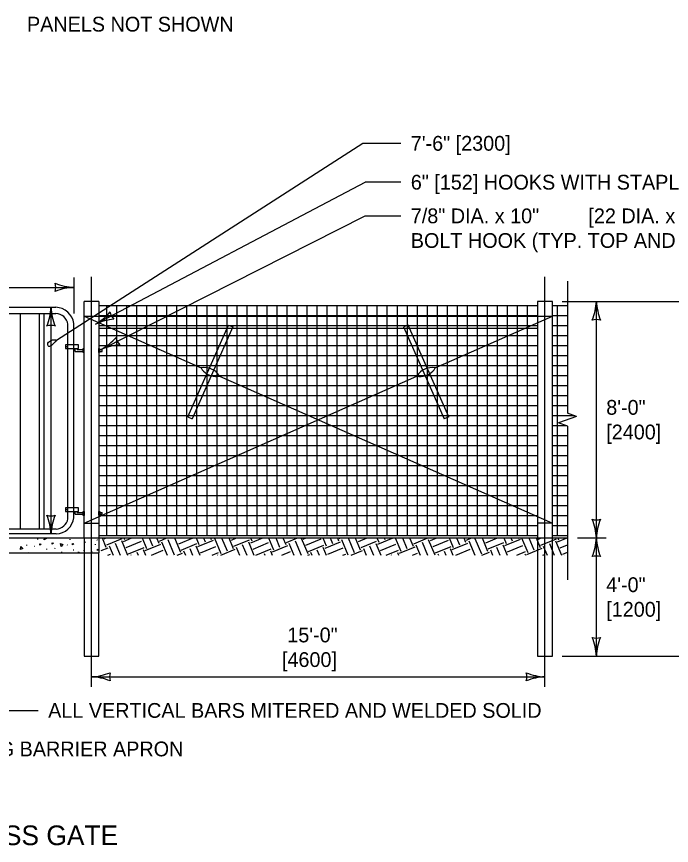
# Model space of a CAD drawing. Extents: x 49991.4 to 50021, y 49987.6 to 50011.4.
# Drawn here: x 50003.24 to 50005.896, y 49992.169 to 49995.535 of the extents above; entities that cross this region are included whole.
import ezdxf

# ---------------------------------------------------------------- set-up
doc = ezdxf.new("R2010")
doc.units = 0
for name, color, linetype in [('Level 1', 7, 'Continuous'), ('Level 2', 7, 'Continuous'), ('Level 3', 7, 'Continuous'), ('Level 4', 7, 'Continuous'), ('Level 5', 7, 'Continuous'), ('Level 6', 7, 'Continuous')]:
    doc.layers.add(name, color=color, linetype=linetype)

msp = doc.modelspace()

# ---------------------------------------------------------------- linework, layer by layer
at = {"layer": 'Level 1'}
for p, q in [((50003.5733, 49994.378), (50003.5133, 49994.378)), ((50003.5133, 49993.4177), (50003.5133, 49994.378)), ((50003.5733, 49994.378), (50003.5733, 49993.3577)), ((50005.4134, 49994.378), (50005.3534, 49994.378)), ((50005.3534, 49994.378), (50005.3534, 49993.4177)), ((50005.4134, 49993.4177), (50005.4134, 49994.378)), ((50002.8238, 49994.3543), (50003.3985, 49994.3543)), ((50005.3534, 49994.3607), (50003.5733, 49994.3607)), ((50003.6058, 49993.4259), (50003.6058, 49994.3607)), ((50003.6464, 49993.4259), (50003.6464, 49994.3607)), ((50003.6871, 49993.4259), (50003.6871, 49994.3607)), ((50003.7277, 49993.4259), (50003.7277, 49994.3607)), ((50003.7683, 49993.4259), (50003.7683, 49994.3607)), ((50003.809, 49993.4259), (50003.809, 49994.3607)), ((50003.8496, 49993.4259), (50003.8496, 49994.3607)), ((50003.8903, 49993.4259), (50003.8903, 49994.3607)), ((50003.9309, 49993.4259), (50003.9309, 49994.3607)), ((50003.9715, 49993.4259), (50003.9715, 49994.3607)), ((50004.0122, 49993.4259), (50004.0122, 49994.3607)), ((50004.0528, 49993.4259), (50004.0528, 49994.3607)), ((50004.0935, 49993.4259), (50004.0935, 49994.3607)), ((50004.1341, 49993.4259), (50004.1341, 49994.3607)), ((50004.1748, 49993.4259), (50004.1748, 49994.3607)), ((50004.2154, 49993.4259), (50004.2154, 49994.3607)), ((50004.256, 49993.4259), (50004.256, 49994.3607)), ((50004.2967, 49993.4259), (50004.2967, 49994.3607)), ((50004.3373, 49993.4259), (50004.3373, 49994.3607)), ((50004.378, 49993.4259), (50004.378, 49994.3607)), ((50004.4186, 49993.4259), (50004.4186, 49994.3607)), ((50004.4592, 49993.4259), (50004.4592, 49994.3607)), ((50004.4999, 49993.4259), (50004.4999, 49994.3607)), ((50004.5405, 49993.4259), (50004.5405, 49994.3607)), ((50004.5812, 49993.4259), (50004.5812, 49994.3607)), ((50004.6218, 49993.4259), (50004.6218, 49994.3607)), ((50004.6625, 49993.4259), (50004.6625, 49994.3607)), ((50004.7031, 49993.4259), (50004.7031, 49994.3607)), ((50004.7437, 49993.4259), (50004.7437, 49994.3607)), ((50004.7844, 49993.4259), (50004.7844, 49994.3607)), ((50004.825, 49993.4259), (50004.825, 49994.3607)), ((50004.8657, 49993.4259), (50004.8657, 49994.3607)), ((50004.9063, 49993.4259), (50004.9063, 49994.3607)), ((50004.947, 49993.4259), (50004.947, 49994.3607)), ((50004.9876, 49993.4259), (50004.9876, 49994.3607)), ((50005.0282, 49993.4259), (50005.0282, 49994.3607)), ((50005.0689, 49993.4259), (50005.0689, 49994.3607)), ((50005.1095, 49993.4259), (50005.1095, 49994.3607)), ((50005.1502, 49993.4259), (50005.1502, 49994.3607)), ((50005.1908, 49993.4259), (50005.1908, 49994.3607)), ((50005.2314, 49993.4259), (50005.2314, 49994.3607)), ((50005.2721, 49993.4259), (50005.2721, 49994.3607)), ((50005.3127, 49993.4259), (50005.3127, 49994.3607)), ((50005.4753, 49994.3607), (50005.4134, 49994.3607)), ((50005.4347, 49993.4259), (50005.4347, 49994.3607)), ((50002.8236, 49994.3293), (50003.3985, 49994.3293)), ((50003.256, 49993.4537), (50003.256, 49994.3293)), ((50003.332, 49993.4537), (50003.332, 49994.3293)), ((50003.352, 49993.4537), (50003.352, 49994.3293)), ((50003.5133, 49994.3179), (50005.4134, 49994.3179)), ((50003.5133, 49994.3179), (50003.9883, 49994.108)), ((50005.3534, 49994.32), (50003.5733, 49994.32)), ((50004.9383, 49994.1079), (50005.4134, 49994.3179)), ((50005.4753, 49994.32), (50005.4134, 49994.32)), ((50003.448, 49993.4957), (50003.448, 49994.2853)), ((50003.472, 49993.4999), (50003.472, 49994.2888)), ((50005.3534, 49994.2794), (50003.5733, 49994.2794)), ((50003.5733, 49994.27), (50005.3534, 49994.27)), ((50003.9337, 49993.9088), (50004.0989, 49994.2823)), ((50004.1172, 49994.2743), (50003.952, 49993.9007)), ((50004.0989, 49994.2823), (50004.1172, 49994.2743)), ((50004.8277, 49994.2824), (50004.8094, 49994.2743)), ((50004.8094, 49994.2743), (50004.9746, 49993.9007)), ((50004.9929, 49993.9088), (50004.8277, 49994.2824)), ((50005.4753, 49994.2794), (50005.4134, 49994.2794)), ((50005.3534, 49994.2387), (50003.5733, 49994.2387)), ((50005.4753, 49994.2387), (50005.4134, 49994.2387)), ((50003.4375, 49994.2014), (50003.4375, 49994.1866)), ((50003.4906, 49994.2014), (50003.4375, 49994.2014)), ((50003.4906, 49994.1866), (50003.4906, 49994.2014)), ((50005.3534, 49994.1981), (50003.5733, 49994.1981)), ((50005.4753, 49994.1981), (50005.4134, 49994.1981)), ((50003.4375, 49994.1866), (50003.4906, 49994.1866)), ((50003.4779, 49994.1752), (50003.4779, 49994.1866)), ((50003.4779, 49994.1752), (50003.5133, 49994.1752)), ((50003.4854, 49994.1827), (50003.4854, 49994.1866)), ((50003.4854, 49994.1827), (50003.5133, 49994.1827)), ((50003.5098, 49994.171), (50003.5098, 49994.1864)), ((50003.5098, 49994.1864), (50003.5133, 49994.1864)), ((50003.5133, 49994.171), (50003.5098, 49994.171)), ((50003.5731, 49994.1711), (50003.5731, 49994.1866)), ((50003.5731, 49994.1866), (50003.5766, 49994.1866)), ((50003.5766, 49994.1711), (50003.5731, 49994.1711)), ((50003.5733, 49994.1752), (50003.5868, 49994.1752)), ((50003.5734, 49994.1827), (50003.5868, 49994.1827)), ((50003.5766, 49994.1866), (50003.5766, 49994.1711)), ((50003.5868, 49994.175), (50003.5868, 49994.1827)), ((50005.3534, 49994.1574), (50003.5733, 49994.1574)), ((50005.4753, 49994.1574), (50005.4134, 49994.1574)), ((50005.3534, 49994.1168), (50003.5733, 49994.1168)), ((50005.4753, 49994.1168), (50005.4134, 49994.1168)), ((50003.5133, 49993.4779), (50004.864, 49994.0751)), ((50005.3534, 49994.0762), (50003.5733, 49994.0762)), ((50004.0626, 49994.0751), (50005.4134, 49993.4779)), ((50005.4753, 49994.0762), (50005.4134, 49994.0762)), ((50005.3534, 49994.0355), (50003.5733, 49994.0355)), ((50005.4753, 49994.0355), (50005.4134, 49994.0355)), ((50005.3534, 49993.9949), (50003.5733, 49993.9949)), ((50005.4753, 49993.9949), (50005.4134, 49993.9949)), ((50005.3534, 49993.9542), (50003.5733, 49993.9542)), ((50005.4753, 49993.9542), (50005.4134, 49993.9542)), ((50005.3534, 49993.9136), (50003.5733, 49993.9136)), ((50003.9337, 49993.9088), (50003.952, 49993.9007)), ((50004.9929, 49993.9088), (50004.9746, 49993.9007)), ((50005.5046, 49993.9136), (50005.4134, 49993.9136)), ((50005.3534, 49993.873), (50003.5733, 49993.873)), ((50005.473, 49993.873), (50005.4134, 49993.873)), ((50005.3534, 49993.8323), (50003.5733, 49993.8323)), ((50005.4753, 49993.8323), (50005.4134, 49993.8323)), ((50005.3534, 49993.7917), (50003.5733, 49993.7917)), ((50005.4753, 49993.7917), (50005.4134, 49993.7917)), ((50005.3534, 49993.751), (50003.5733, 49993.751)), ((50005.4753, 49993.751), (50005.4134, 49993.751)), ((50005.3534, 49993.7104), (50003.5733, 49993.7104)), ((50005.4753, 49993.7104), (50005.4134, 49993.7104)), ((50005.3534, 49993.6697), (50003.5733, 49993.6697)), ((50005.4753, 49993.6697), (50005.4134, 49993.6697)), ((50005.3534, 49993.6291), (50003.5733, 49993.6291)), ((50005.4753, 49993.6291), (50005.4134, 49993.6291)), ((50005.3534, 49993.5885), (50003.5733, 49993.5885)), ((50005.4753, 49993.5885), (50005.4134, 49993.5885)), ((50003.4779, 49993.5136), (50003.4779, 49993.525)), ((50003.4854, 49993.5211), (50003.4854, 49993.525)), ((50005.3534, 49993.5478), (50003.5733, 49993.5478)), ((50005.4753, 49993.5478), (50005.4134, 49993.5478)), ((50003.4779, 49993.5136), (50003.5133, 49993.5136)), ((50003.4854, 49993.5211), (50003.5133, 49993.5211)), ((50003.5733, 49993.5211), (50003.5868, 49993.5211)), ((50003.5733, 49993.5136), (50003.5868, 49993.5136)), ((50005.3534, 49993.5072), (50003.5733, 49993.5072)), ((50003.5868, 49993.5136), (50003.5868, 49993.5211)), ((50005.4753, 49993.5072), (50005.4134, 49993.5072)), ((50003.5133, 49993.4779), (50003.5733, 49993.4779)), ((50005.3534, 49993.4665), (50003.5733, 49993.4665)), ((50005.4134, 49993.4779), (50005.3534, 49993.4779)), ((50005.4753, 49993.4665), (50005.4134, 49993.4665)), ((50003.4, 49993.4537), (50002.8253, 49993.4537)), ((50003.4, 49993.4337), (50002.8253, 49993.4337)), ((50005.3534, 49993.4259), (50003.5733, 49993.4259)), ((50005.4753, 49993.4259), (50005.4134, 49993.4259)), ((49999.9385, 49993.4177), (50005.4753, 49993.4177)), ((50003.326, 49993.4113), (50003.3261, 49993.4134)), ((50003.4451, 49993.3898), (50003.446, 49993.3881)), ((50003.4574, 49993.4104), (50003.4575, 49993.4126)), ((50003.4913, 49993.4148), (50003.4913, 49993.4169)), ((50003.5191, 49993.3991), (50003.5191, 49993.4013)), ((50003.5595, 49993.3899), (50003.5595, 49993.392)), ((50003.5651, 49993.4096), (50003.5664, 49993.4087)), ((50003.5661, 49993.4094), (50003.5674, 49993.4086)), ((50003.5866, 49993.4177), (50003.602, 49993.3807)), ((50003.5953, 49993.4146), (50003.6028, 49993.4177)), ((50003.6056, 49993.3896), (50003.6683, 49993.4155)), ((50003.64, 49993.3965), (50003.6603, 49993.3476)), ((50003.6651, 49993.4068), (50003.6896, 49993.3476)), ((50003.6733, 49993.4034), (50003.7078, 49993.4177)), ((50003.6747, 49993.4177), (50003.6771, 49993.4118)), ((50003.6837, 49993.3784), (50003.7463, 49993.4043)), ((50003.7486, 49993.4177), (50003.7662, 49993.3754)), ((50003.7618, 49993.3667), (50003.8245, 49993.3927)), ((50003.7779, 49993.4177), (50003.7912, 49993.3857)), ((50003.8073, 49993.4177), (50003.8163, 49993.3961)), ((50003.8193, 49993.4052), (50003.8495, 49993.4177)), ((50003.8281, 49993.4015), (50003.8505, 49993.3476)), ((50003.8532, 49993.4119), (50003.8791, 49993.3493)), ((50003.8801, 49993.4177), (50003.9042, 49993.3597)), ((50003.8975, 49993.3936), (50003.9558, 49993.4177)), ((50003.9078, 49993.3685), (50003.9705, 49993.3945)), ((50003.9682, 49993.4177), (50003.9793, 49993.3908)), ((50003.9755, 49993.3824), (50004.0381, 49993.4083)), ((50003.9975, 49993.4177), (50004.0044, 49993.4012)), ((50004.0269, 49993.4177), (50004.0294, 49993.4115)), ((50004.0424, 49993.4169), (50004.0683, 49993.3543)), ((50004.0714, 49993.4177), (50004.0934, 49993.3647)), ((50004.1008, 49993.4177), (50004.1184, 49993.3751)), ((50004.1111, 49993.4092), (50004.1317, 49993.4177)), ((50004.1215, 49993.3842), (50004.1841, 49993.4101)), ((50004.1554, 49993.3909), (50004.1733, 49993.3476)), ((50004.1804, 49993.4012), (50004.2027, 49993.3476)), ((50004.1888, 49993.4177), (50004.1936, 49993.4062)), ((50004.1893, 49993.3976), (50004.238, 49993.4177)), ((50004.1997, 49993.3725), (50004.2623, 49993.3985)), ((50004.2182, 49993.4177), (50004.2186, 49993.4166)), ((50004.2616, 49993.4177), (50004.2815, 49993.3697)), ((50004.291, 49993.4177), (50004.3066, 49993.3801)), ((50004.3203, 49993.4177), (50004.3316, 49993.3905)), ((50004.3353, 49993.3994), (50004.3797, 49993.4177)), ((50004.3446, 49993.3959), (50004.3646, 49993.3476)), ((50004.3696, 49993.4062), (50004.394, 49993.3476)), ((50004.3947, 49993.4166), (50004.4206, 49993.354)), ((50004.4029, 49993.4132), (50004.4138, 49993.4177)), ((50004.4133, 49993.3882), (50004.4759, 49993.4141)), ((50004.4823, 49993.4177), (50004.4958, 49993.3851)), ((50004.4915, 49993.3765), (50004.5541, 49993.4025)), ((50004.5116, 49993.4177), (50004.5208, 49993.3955)), ((50004.541, 49993.4177), (50004.5459, 49993.4059)), ((50004.5489, 49993.415), (50004.5555, 49993.4177)), ((50004.5578, 49993.4113), (50004.5837, 49993.3487)), ((50004.5845, 49993.4177), (50004.6088, 49993.3591)), ((50004.6138, 49993.4177), (50004.6338, 49993.3694)), ((50004.6271, 49993.4034), (50004.6618, 49993.4177)), ((50004.6375, 49993.3783), (50004.7001, 49993.4042)), ((50004.6969, 49993.3956), (50004.7168, 49993.3476)), ((50004.7018, 49993.4177), (50004.709, 49993.4006)), ((50004.7051, 49993.3922), (50004.7669, 49993.4177)), ((50004.7155, 49993.3671), (50004.7781, 49993.393)), ((50004.7312, 49993.4177), (50004.734, 49993.4109)), ((50004.7757, 49993.4177), (50004.798, 49993.3641)), ((50004.8051, 49993.4177), (50004.823, 49993.3745)), ((50004.8344, 49993.4177), (50004.8481, 49993.3848)), ((50004.8511, 49993.3939), (50004.9086, 49993.4177)), ((50004.86, 49993.3903), (50004.8776, 49993.3476)), ((50004.885, 49993.4006), (50004.907, 49993.3476)), ((50004.9101, 49993.411), (50004.936, 49993.3484)), ((50004.9189, 49993.4073), (50004.944, 49993.4177)), ((50004.9225, 49993.4177), (50004.9232, 49993.416)), ((50004.9293, 49993.3823), (50004.9919, 49993.4082)), ((50004.9953, 49993.4177), (50005.0111, 49993.3795)), ((50005.0073, 49993.3711), (50005.0699, 49993.397)), ((50005.0247, 49993.4177), (50005.0362, 49993.3899)), ((50005.054, 49993.4177), (50005.0612, 49993.4003)), ((50005.0649, 49993.4091), (50005.0857, 49993.4177)), ((50005.0742, 49993.4057), (50005.0983, 49993.3476)), ((50005.0993, 49993.416), (50005.1252, 49993.3534)), ((50005.1279, 49993.4177), (50005.1503, 49993.3638)), ((50005.1429, 49993.3979), (50005.1907, 49993.4177)), ((50005.1533, 49993.3729), (50005.2159, 49993.3988)), ((50005.2122, 49993.39), (50005.2298, 49993.3476)), ((50005.216, 49993.4177), (50005.2254, 49993.3949)), ((50005.2211, 49993.3863), (50005.2837, 49993.4122)), ((50005.2453, 49993.4177), (50005.2505, 49993.4053)), ((50005.2747, 49993.4177), (50005.2755, 49993.4157)), ((50005.2888, 49993.4177), (50005.3133, 49993.3585)), ((50005.3181, 49993.4177), (50005.3384, 49993.3688)), ((50005.3475, 49993.4177), (50005.3634, 49993.3792)), ((50005.3567, 49993.4131), (50005.3678, 49993.4177)), ((50005.3671, 49993.3881), (50005.4297, 49993.414)), ((50005.4015, 49993.395), (50005.4211, 49993.3476)), ((50005.4265, 49993.4054), (50005.4505, 49993.3476)), ((50005.4347, 49993.4019), (50005.4729, 49993.4177)), ((50005.4355, 49993.4177), (50005.4386, 49993.4103)), ((50005.4451, 49993.3769), (50005.4753, 49993.3894)), ((50001.8892, 49993.3577), (50003.5733, 49993.3577)), ((50003.2805, 49993.3871), (50003.2806, 49993.3892)), ((50003.3109, 49993.3846), (50003.3121, 49993.3838)), ((50003.3616, 49993.3707), (50003.3617, 49993.3729)), ((50003.3954, 49993.3751), (50003.3955, 49993.3773)), ((50003.4232, 49993.3595), (50003.4233, 49993.3616)), ((50003.4693, 49993.3699), (50003.4706, 49993.369)), ((50003.4703, 49993.3698), (50003.4716, 49993.3689)), ((50003.514, 49993.3656), (50003.514, 49993.3677)), ((50003.5443, 49993.3632), (50003.5456, 49993.3623)), ((50003.5828, 49993.366), (50003.6107, 49993.3775)), ((50003.615, 49993.3861), (50003.6309, 49993.3476)), ((50003.694, 49993.3533), (50003.7567, 49993.3793)), ((50003.7279, 49993.36), (50003.7331, 49993.3476)), ((50003.753, 49993.3704), (50003.7624, 49993.3476)), ((50003.7864, 49993.3476), (50003.8348, 49993.3676)), ((50003.8914, 49993.3476), (50003.9128, 49993.3564)), ((50003.9172, 49993.365), (50003.9244, 49993.3476)), ((50003.9422, 49993.3754), (50003.9537, 49993.3476)), ((50003.9673, 49993.3858), (50003.9831, 49993.3476)), ((50003.9858, 49993.3573), (50004.0485, 49993.3833)), ((50004.0331, 49993.3476), (50004.0588, 49993.3582)), ((50004.0686, 49993.3476), (50004.1267, 49993.3716)), ((50004.1303, 49993.3805), (50004.144, 49993.3476)), ((50004.2103, 49993.3476), (50004.2727, 49993.3734)), ((50004.2694, 49993.3647), (50004.2766, 49993.3476)), ((50004.2777, 49993.3613), (50004.3403, 49993.3873)), ((50004.3153, 49993.3476), (50004.3507, 49993.3622)), ((50004.4237, 49993.3631), (50004.4863, 49993.389)), ((50004.4325, 49993.3594), (50004.4374, 49993.3476)), ((50004.4576, 49993.3698), (50004.4668, 49993.3476)), ((50004.4826, 49993.3802), (50004.4961, 49993.3476)), ((50004.5018, 49993.3515), (50004.5645, 49993.3774)), ((50004.5975, 49993.3476), (50004.6425, 49993.3662)), ((50004.6468, 49993.3748), (50004.6581, 49993.3476)), ((50004.6718, 49993.3852), (50004.6874, 49993.3476)), ((50004.7392, 49993.3476), (50004.7885, 49993.368)), ((50004.7848, 49993.3591), (50004.7896, 49993.3476)), ((50004.7937, 49993.3555), (50004.8563, 49993.3814)), ((50004.8454, 49993.3476), (50004.8667, 49993.3564)), ((50004.9397, 49993.3573), (50005.0023, 49993.3832)), ((50004.974, 49993.3641), (50004.9809, 49993.3476)), ((50004.9991, 49993.3745), (50005.0102, 49993.3476)), ((50005.0213, 49993.3476), (50005.0803, 49993.372)), ((50005.1276, 49993.3476), (50005.1585, 49993.3604)), ((50005.1621, 49993.3692), (50005.1711, 49993.3476)), ((50005.1872, 49993.3796), (50005.2005, 49993.3476)), ((50005.2315, 49993.3612), (50005.2941, 49993.3872)), ((50005.2693, 49993.3476), (50005.3045, 49993.3621)), ((50005.3095, 49993.3501), (50005.3721, 49993.376)), ((50005.3764, 49993.3846), (50005.3918, 49993.3476)), ((50005.4555, 49993.3518), (50005.4753, 49993.36)), ((50003.6093, 49993.3476), (50003.621, 49993.3524)), ((50003.7029, 49993.3497), (50003.7037, 49993.3476)), ((50004.0552, 49993.3494), (50004.0559, 49993.3476)), ((50004.2444, 49993.3544), (50004.2472, 49993.3476)), ((50004.4216, 49993.3476), (50004.4288, 49993.3506)), ((50004.5633, 49993.3476), (50004.5748, 49993.3524)), ((50004.7598, 49993.3488), (50004.7603, 49993.3476)), ((50004.949, 49993.3538), (50004.9515, 49993.3476)), ((50005.3013, 49993.3535), (50005.3037, 49993.3476)), ((50005.3743, 49993.3476), (50005.3825, 49993.3509)), ((50005.4643, 49993.3482), (50005.4646, 49993.3476))]:
    msp.add_line(p, q, dxfattribs=at)
for points in [[(50003.4906, 49993.525), (50003.4906, 49993.5397), (50003.4375, 49993.5397), (50003.4375, 49993.525)], [(50003.5133, 49993.5248), (50003.5133, 49993.5093), (50003.5098, 49993.5093), (50003.5098, 49993.5248)], [(50003.5768, 49993.5249), (50003.5768, 49993.5095), (50003.5733, 49993.5095), (50003.5733, 49993.5249)]]:
    msp.add_lwpolyline(points, close=True, dxfattribs=at)
for points in [[(50003.334, 49993.3881), (50003.3343, 49993.3941), (50003.3396, 49993.3928), (50003.334, 49993.3881)], [(50003.3516, 49993.4102), (50003.3523, 49993.4177)], [(50003.3579, 49993.4177), (50003.3609, 49993.415), (50003.3518, 49993.4103)], [(50003.3838, 49993.392), (50003.3841, 49993.398), (50003.3894, 49993.3966), (50003.3838, 49993.392)], [(50003.4206, 49993.3831), (50003.4175, 49993.3952), (50003.4277, 49993.3908), (50003.4208, 49993.3833)], [(50003.4665, 49993.3896), (50003.4669, 49993.3956), (50003.4721, 49993.3942), (50003.4665, 49993.3896)], [(50003.2558, 49993.3705), (50003.2569, 49993.3829), (50003.265, 49993.3753), (50003.256, 49993.3706)], [(50003.2883, 49993.3577), (50003.2883, 49993.3583), (50003.2905, 49993.3577)], [(50003.49, 49993.3577), (50003.4904, 49993.3615), (50003.4943, 49993.3577)], [(50003.5674, 49993.3667), (50003.5678, 49993.3727), (50003.573, 49993.3713), (50003.5674, 49993.3667)]]:
    msp.add_lwpolyline(points, dxfattribs=at)
for centre in [(50003.4426, 49994.1943), (50003.4426, 49993.5327)]:
    msp.add_circle(centre, 0.00125, dxfattribs=at)
for centre, radius, start, end in [((50003.3965, 49994.2781), 0.0762, 8.0258, 88.4771), ((50003.3971, 49994.2781), 0.0512, 8.0258, 88.4771), ((50004.0027, 49994.0401), 0.0694, 30.2786, 102.0153), ((50004.0482, 49994.1429), 0.0694, 210.2889, 237.8723), ((50004.9239, 49994.0401), 0.0694, 77.9855, 149.7127), ((50004.8784, 49994.1429), 0.0694, 302.146, 329.7119), ((50004.0482, 49994.1429), 0.0694, 254.4343, 282.0085), ((50004.8784, 49994.1429), 0.0694, 257.9863, 285.5691), ((50003.3964, 49993.5098), 0.0762, 272.7386, 352.5107), ((50003.3976, 49993.5048), 0.0512, 272.7386, 349.801)]:
    msp.add_arc(centre, radius, start, end, dxfattribs=at)
at = {"layer": 'Level 3'}
for p, q in [((50003.401, 49994.2208), (50004.6438, 49995.0202)), ((50004.6438, 49995.0202), (50004.799, 49995.0202)), ((50003.5591, 49994.2852), (50004.6536, 49994.8623)), ((50004.799, 49994.8623), (50004.6536, 49994.8623)), ((50003.5826, 49994.1827), (50004.6535, 49994.7256)), ((50004.6535, 49994.7256), (50004.799, 49994.7256)), ((50003.472, 49994.4753), (50003.472, 49994.3288)), ((50002.7519, 49994.4353), (50003.472, 49994.4353)), ((50005.4534, 49994.378), (50006.0156, 49994.378)), ((50005.592, 49993.4177), (50005.592, 49994.378)), ((50003.3792, 49993.4337), (50003.3792, 49994.3544)), ((50005.5153, 49993.4177), (50005.632, 49993.4177)), ((50005.592, 49992.9379), (50005.592, 49993.4177)), ((50005.4534, 49992.938), (50006.0156, 49992.938)), ((50003.5433, 49992.8537), (50005.3834, 49992.8537)), ((50003.1823, 49992.7172), (50003.3277, 49992.7172))]:
    msp.add_line(p, q, dxfattribs=at)
for centre, radius, start, end in [((50003.4811, 49994.6574), 0.2223, 247.456, 267.6395), ((50003.3438, 49994.4353), 0.0548, 342.1388, 17.8612), ((50003.4835, 49994.2026), 0.233, 92.8273, 112.0772), ((50005.3699, 49994.3872), 0.2223, 337.456, 357.6395), ((50005.8247, 49994.3895), 0.233, 182.8273, 202.0772), ((50003.157, 49994.3635), 0.2223, 337.456, 357.6395), ((50003.6119, 49994.3659), 0.233, 182.8273, 202.0772), ((50003.4404, 49994.4857), 0.233, 300.6297, 319.8795), ((50003.6725, 49994.345), 0.0548, 189.9412, 225.6636), ((50003.6546, 49994.0844), 0.2223, 95.2584, 115.4419), ((50005.592, 49994.2498), 0.0548, 72.1388, 107.8612), ((50003.3792, 49994.2262), 0.0548, 72.1388, 107.8612), ((50003.4672, 49994.3851), 0.233, 299.7105, 318.9604), ((50003.697, 49994.2407), 0.0548, 189.0221, 224.7444), ((50003.6749, 49993.9804), 0.2223, 94.3392, 114.5228), ((50003.3792, 49993.562), 0.0548, 252.1388, 287.8612), ((50003.1464, 49993.4223), 0.233, 2.8273, 22.0772), ((50003.6013, 49993.4246), 0.2223, 157.456, 177.6395), ((50005.592, 49993.5459), 0.0548, 252.1388, 287.8612), ((50005.3593, 49993.4062), 0.233, 2.8273, 22.0772), ((50005.8141, 49993.4086), 0.2223, 157.456, 177.6395), ((50005.3699, 49993.4269), 0.2223, 337.456, 357.6395), ((50005.8247, 49993.4292), 0.233, 182.8273, 202.0772), ((50005.592, 49993.2895), 0.0548, 72.1388, 107.8612), ((50005.592, 49993.0661), 0.0548, 252.1388, 287.8612), ((50005.3593, 49992.9264), 0.233, 2.8273, 22.0772), ((50005.8141, 49992.9288), 0.2223, 157.456, 177.6395), ((50003.5318, 49993.0864), 0.233, 272.8273, 292.0772), ((50003.5341, 49992.6316), 0.2223, 67.456, 87.6395), ((50003.6715, 49992.8537), 0.0548, 162.1388, 197.8612), ((50005.3925, 49993.0758), 0.2223, 247.456, 267.6395), ((50005.2552, 49992.8537), 0.0548, 342.1388, 17.8612), ((50005.3949, 49992.621), 0.233, 92.8273, 112.0772)]:
    msp.add_arc(centre, radius, start, end, dxfattribs=at)
msp.add_spline([(50003.401, 49994.2208), (50003.3679, 49994.1975), (50003.3668, 49994.2085), (50003.382, 49994.2206), (50003.3951, 49994.2226), (50003.4012, 49994.2206)], degree=3, dxfattribs=at)
at = {"layer": 'Level 4'}
for p, q in [((50003.5133, 49993.4177), (50003.5133, 49992.9379)), ((50005.3534, 49993.4177), (50005.3534, 49992.9379)), ((50005.4134, 49992.9379), (50005.4134, 49993.4177)), ((50003.5733, 49992.9379), (50003.5733, 49993.3577)), ((50003.5133, 49992.9379), (50003.5733, 49992.9379)), ((50005.3534, 49992.9379), (50005.4134, 49992.9379))]:
    msp.add_line(p, q, dxfattribs=at)
for centre, start, end in [((50004.0482, 49994.1429), 237.8574, 254.4343), ((50004.8784, 49994.1429), 285.5691, 302.146)]:
    msp.add_arc(centre, 0.0694, start, end, dxfattribs=at)
at = {"layer": 'Level 5'}
for p, q in [((50003.5433, 49992.8137), (50003.5433, 49994.478)), ((50005.3834, 49992.8137), (50005.3834, 49994.478))]:
    msp.add_line(p, q, dxfattribs=at)
at = {"layer": 'Level 6'}
for p, q in [((50005.4753, 49994.4607), (50005.4753, 49993.924)), ((50005.5119, 49993.911), (50005.4387, 49993.8851)), ((50005.5119, 49993.911), (50005.4753, 49993.924)), ((50005.4753, 49993.8721), (50005.4387, 49993.8851)), ((50005.4753, 49993.8721), (50005.4753, 49993.2475))]:
    msp.add_line(p, q, dxfattribs=at)

# ---------------------------------------------------------------- texts
at = {"layer": 'Level 2'}
for s, height, p in [('PANELS NOT SHOWN', 0.06, (50003.2819, 49995.474)), ('7\'-6" [2300]', 0.060003, (50004.839, 49994.9902)), ('6" [152] HOOKS WITH STAPLES', 0.060003, (50004.839, 49994.8323)), ('7/8" DIA. x 10" ', 0.060003, (50004.839, 49994.6956)), ('[22 DIA. x 254] ', 0.060003, (50005.5596, 49994.6956)), ('BOLT HOOK (TYP. TOP AND BOTTOM)', 0.060003, (50004.839, 49994.5956)), ('8\'-0"', 0.06, (50005.632, 49993.9179)), ('[2400]', 0.06, (50005.632, 49993.8179)), ('4\'-0"', 0.06, (50005.632, 49993.1978)), ('[1200]', 0.06, (50005.632, 49993.0978)), ('15\'-0"', 0.06, (50004.3379, 49992.9937)), ('[4600]', 0.06, (50004.3162, 49992.8937)), ('ALL VERTICAL BARS MITERED AND WELDED SOLID', 0.060003, (50003.3677, 49992.6872)), ('CONCRETE DIG BARRIER APRON', 0.060003, (50002.6144, 49992.5308)), ('METAL MAINTENANCE ACCESS GATE', 0.08, (50001.696, 49992.1701))]:
    msp.add_text(s, height=height, dxfattribs=at).set_placement(p)

doc.saveas('drawing.dxf')
